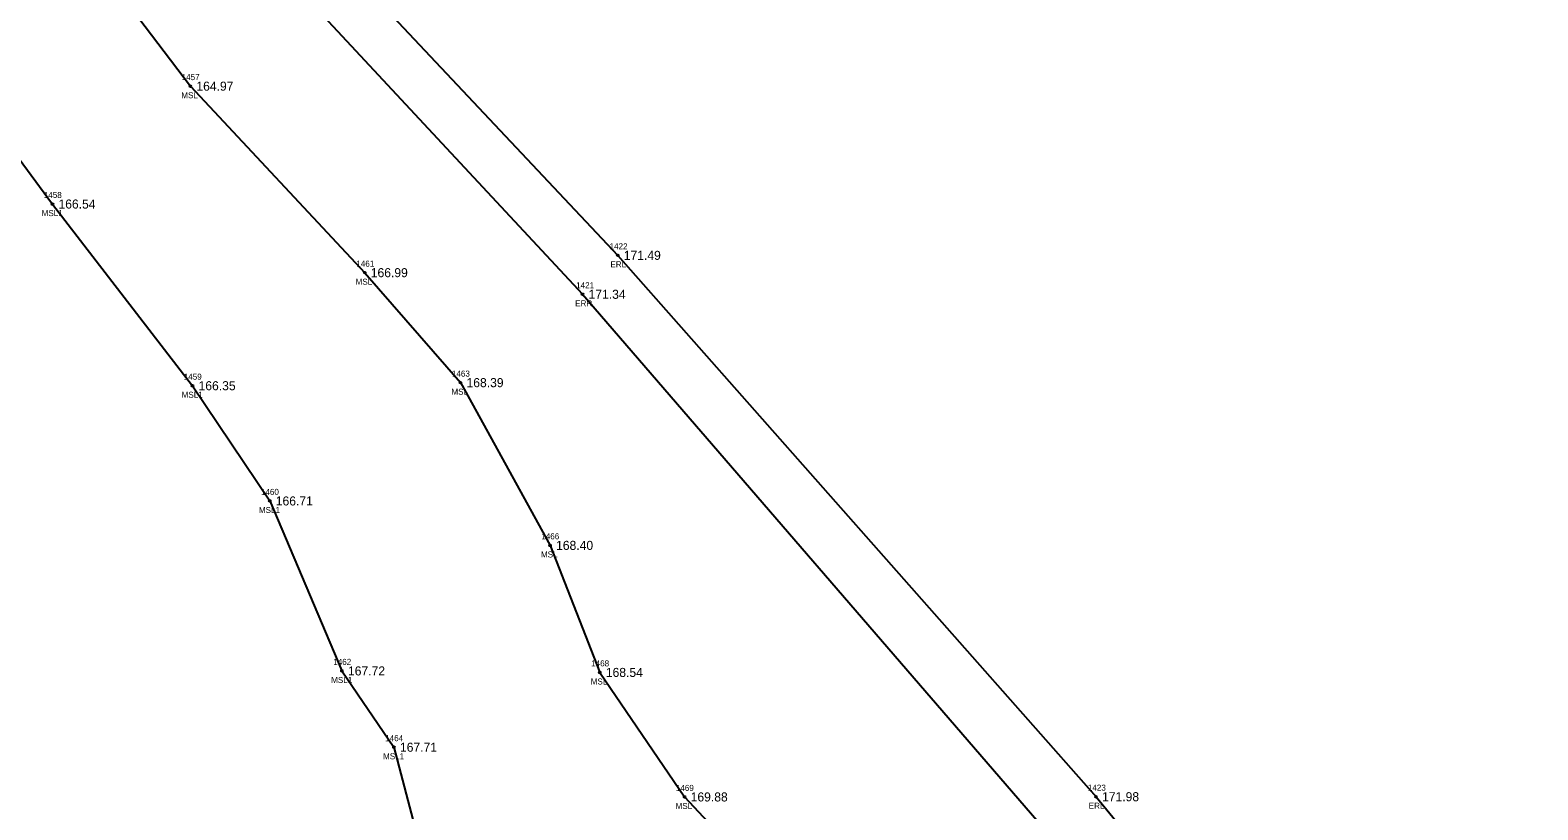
# Model space of a CAD drawing. Extents: x 1969685 to 1970577, y 796315 to 797503.
# Drawn here: x 1970128.7 to 1970378.4, y 796838.1 to 796967.3 of the extents above; entities that cross this region are included whole.
import ezdxf

# ---------------------------------------------------------------- set-up
doc = ezdxf.new("R2010")
doc.units = 0
for name, color, linetype in [('RD_EX_Misc', 7, 'Continuous'), ('RD_EX_Misc_txCode', 7, 'Continuous'), ('RD_EX_Road', 7, 'Continuous'), ('RD_EX_Road_txCode', 7, 'Continuous'), ('RD_EX_TX_Misc_ELEV', 7, 'Continuous'), ('RD_EX_TX_Road_ELEV', 7, 'Continuous'), ('RD_SMD_Locator', 7, 'Continuous')]:
    doc.layers.add(name, color=color, linetype=linetype)

msp = doc.modelspace()

# ---------------------------------------------------------------- linework, layer by layer
at = {"layer": 'RD_EX_Misc'}
for points in [[(1970119.68, 797002.07), (1970134.67, 796985.14), (1970155.26, 796957.98), (1970184.14, 796927.08), (1970200, 796908.86), (1970214.83, 796881.9), (1970223.07, 796860.85), (1970237.12, 796840.22), (1970247.97, 796828.57), (1970264.98, 796797.04), (1970268.55, 796760.45), (1970285.4, 796719.08), (1970289.98, 796692.37), (1970293.21, 796649.04), (1970312.17, 796610.64), (1970319.99, 796568.49), (1970324.17, 796540.99), (1970330.09, 796500.77), (1970344.67, 796440.73), (1970352.86, 796398.26), (1970358.68, 796366.34), (1970371.75, 796316.87)], [(1970114.12, 796963.3), (1970132.42, 796938.45), (1970155.62, 796908.35), (1970168.41, 796889.26), (1970180.37, 796861.1), (1970188.98, 796848.46), (1970192.73, 796834.16), (1970222.29, 796768.03), (1970236.51, 796684.05), (1970250.88, 796649.74), (1970268.59, 796625.9), (1970285.6, 796558.95), (1970297.61, 796519.29), (1970305.78, 796473.65), (1970318, 796423.32), (1970326.24, 796374.48), (1970344.95, 796321.79)]]:
    msp.add_lwpolyline(points, dxfattribs=at)
at = {"layer": 'RD_EX_Road'}
for points in [[(1969700.74, 797501.33), (1969779.98, 797423.39), (1969814.72, 797391.2), (1969880.84, 797321.11), (1969950.92, 797234.98), (1970023.24, 797160.71), (1970094.63, 797082.52), (1970155.94, 797004.5), (1970226.04, 796929.95), (1970305.25, 796840.26), (1970331.41, 796808.37), (1970366.95, 796762.12), (1970420.55, 796674.34), (1970475.41, 796571.94), (1970519.62, 796482.24), (1970570.43, 796387.6)], [(1969686.81, 797489.23), (1969769.62, 797412.05), (1969806.95, 797381.52), (1969873.82, 797315.12), (1969942.63, 797227.86), (1970016.3, 797154.94), (1970086.97, 797075.58), (1970150.3, 796998.65), (1970220.21, 796923.5), (1970297.55, 796833.97), (1970324.51, 796802.07), (1970359.87, 796756.6), (1970413.8, 796671.17), (1970467.81, 796568.38), (1970512.42, 796477.88), (1970563.2, 796383.6)]]:
    msp.add_lwpolyline(points, dxfattribs=at)
at = {"layer": 'RD_SMD_Locator'}
for centre in [(1970155.26, 796957.98), (1970132.42, 796938.45), (1970226.04, 796929.95), (1970184.14, 796927.08), (1970220.21, 796923.5), (1970155.62, 796908.35), (1970200, 796908.86), (1970168.41, 796889.26), (1970214.83, 796881.9), (1970180.37, 796861.1), (1970223.07, 796860.85), (1970188.98, 796848.46), (1970237.12, 796840.22), (1970305.25, 796840.26)]:
    msp.add_circle(centre, 0.15, dxfattribs=at)

# ---------------------------------------------------------------- texts
at = {"layer": 'RD_EX_Misc_txCode'}
for s, p in [('1457', (1970153.82, 796958.98)), ('MSL', (1970153.76, 796955.98)), ('1458', (1970130.99, 796939.45)), ('MSL1', (1970130.63, 796936.45)), ('1461', (1970182.75, 796928.08)), ('MSL', (1970182.63, 796925.08)), ('1459', (1970154.17, 796909.35)), ('1463', (1970198.58, 796909.86)), ('MSL', (1970198.5, 796906.86)), ('MSL1', (1970153.82, 796906.35)), ('1460', (1970166.95, 796890.26)), ('MSL1', (1970166.61, 796887.26)), ('1466', (1970213.38, 796882.9)), ('MSL', (1970213.32, 796879.9)), ('1462', (1970178.93, 796862.1)), ('1468', (1970221.64, 796861.85)), ('MSL1', (1970178.58, 796859.1)), ('MSL', (1970221.57, 796858.85)), ('1464', (1970187.53, 796849.46)), ('MSL1', (1970187.18, 796846.46)), ('1469', (1970235.67, 796841.22)), ('MSL', (1970235.62, 796838.22))]:
    msp.add_text(s, height=1, dxfattribs=at).set_placement(p)
at = {"layer": 'RD_EX_Road_txCode'}
for s, p in [('1422', (1970224.69, 796930.95)), ('ERL', (1970224.83, 796927.95)), ('1421', (1970219.15, 796924.5)), ('ERR', (1970218.99, 796921.5)), ('1423', (1970303.9, 796841.26)), ('ERL', (1970304.04, 796838.26))]:
    msp.add_text(s, height=1, dxfattribs=at).set_placement(p)
at = {"layer": 'RD_EX_TX_Misc_ELEV'}
for s, p in [('164.97', (1970156.26, 796957.23)), ('166.54', (1970133.42, 796937.7)), ('166.99', (1970185.14, 796926.33)), ('166.35', (1970156.62, 796907.6)), ('168.39', (1970201, 796908.11)), ('166.71', (1970169.41, 796888.51)), ('168.40', (1970215.83, 796881.15)), ('167.72', (1970181.37, 796860.35)), ('168.54', (1970224.07, 796860.1)), ('167.71', (1970189.98, 796847.71)), ('169.88', (1970238.12, 796839.47))]:
    msp.add_text(s, height=1.5, dxfattribs=at).set_placement(p)
at = {"layer": 'RD_EX_TX_Road_ELEV'}
for s, p in [('171.49', (1970227.04, 796929.2)), ('171.34', (1970221.21, 796922.75)), ('171.98', (1970306.25, 796839.51))]:
    msp.add_text(s, height=1.5, dxfattribs=at).set_placement(p)

doc.saveas('drawing.dxf')
